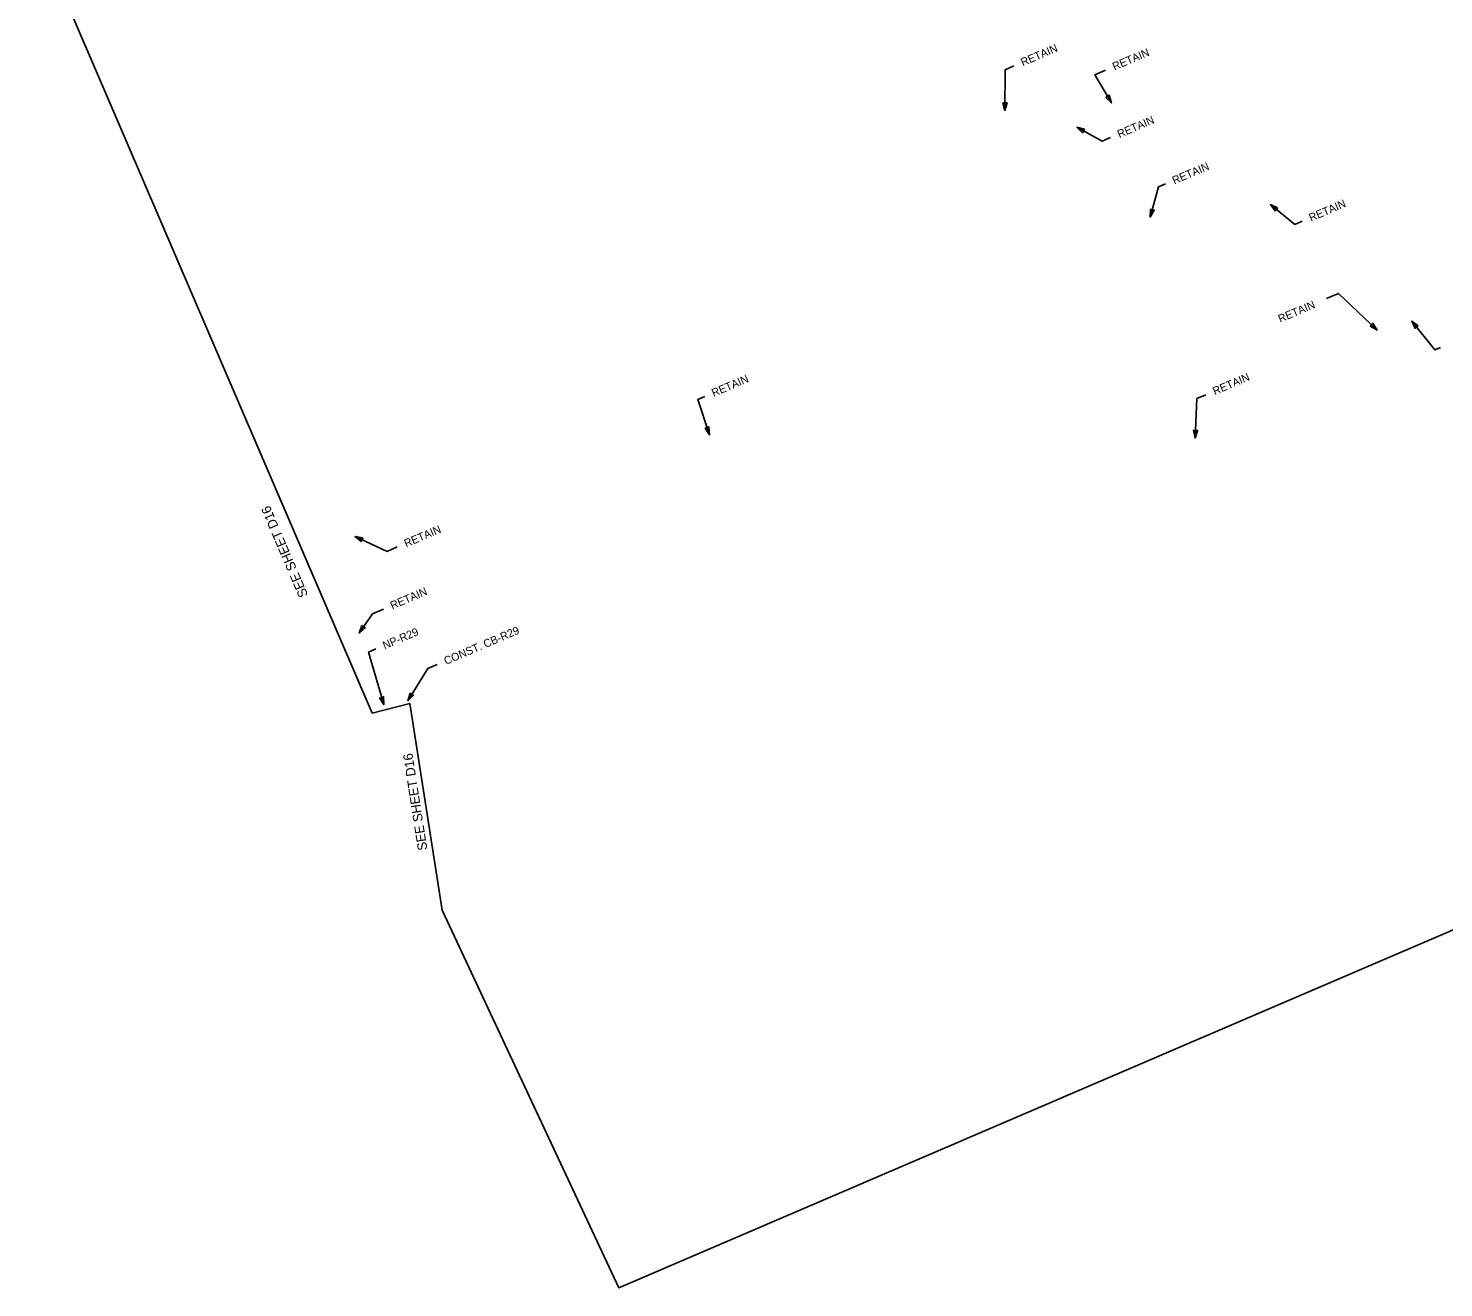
# Model space of a CAD drawing. Extents: x 1621083 to 1622865, y 1102384 to 1104005.
# Drawn here: x 1621083 to 1621976, y 1102384 to 1103179 of the extents above; entities that cross this region are included whole.
import ezdxf

# ---------------------------------------------------------------- set-up
doc = ezdxf.new("R2010")
doc.units = 0
for name, color, linetype in [('Level 8', 7, 'Continuous'), ('RD_HC_Data_Tic', 7, 'Continuous'), ('RFP', 7, 'Continuous')]:
    doc.layers.add(name, color=color, linetype=linetype)

msp = doc.modelspace()

# ---------------------------------------------------------------- linework, layer by layer
at = {"layer": 'Level 8'}
for points in [[(1621705.14, 1103155.41), (1621699.52, 1103153), (1621699.47, 1103127.29)], [(1621762.96, 1103152.74), (1621756.16, 1103149.82), (1621766.63, 1103132.03)], [(1621766.08, 1103110.09), (1621760.85, 1103107.84), (1621744.84, 1103116.66)], [(1621800.73, 1103080.85), (1621796.33, 1103078.96), (1621791.17, 1103059.95)], [(1621886.97, 1103057.32), (1621882.43, 1103055.37), (1621866.93, 1103067.88)], [(1621902.44, 1103008.5), (1621910, 1103011.74), (1621934.27, 1102988.65)], [(1621974.23, 1102977.64), (1621970.6, 1102976.08), (1621956.22, 1102994.32)], [(1621510.07, 1102946.72), (1621505.65, 1102944.83), (1621512.95, 1102922.47)], [(1621826.26, 1102947.82), (1621820.5, 1102945.35), (1621819.46, 1102920.51)], [(1621316.04, 1102851.73), (1621309.57, 1102848.95), (1621289.39, 1102858.31)], [(1621307.31, 1102812.53), (1621300.39, 1102809.56), (1621291.99, 1102797.4)], [(1621302.51, 1102787.33), (1621297.86, 1102785.33), (1621307.45, 1102752.2)], [(1621341.17, 1102777.53), (1621335.28, 1102775.01), (1621322.71, 1102754.68)]]:
    msp.add_lwpolyline(points, dxfattribs=at)
for points in [[(1621698.19, 1103132.12), (1621699.47, 1103127.29), (1621700.77, 1103132.12)], [(1621763.07, 1103135.53), (1621766.63, 1103132.03), (1621765.3, 1103136.84)], [(1621749.7, 1103115.46), (1621744.84, 1103116.66), (1621748.45, 1103113.19)], [(1621871.5, 1103065.85), (1621866.93, 1103067.88), (1621869.88, 1103063.84)], [(1621791.18, 1103064.95), (1621791.17, 1103059.95), (1621793.68, 1103064.27)], [(1621929.88, 1102991.04), (1621934.27, 1102988.65), (1621931.66, 1102992.91)], [(1621960.22, 1102991.33), (1621956.22, 1102994.32), (1621958.19, 1102989.72)], [(1621510.22, 1102926.66), (1621512.95, 1102922.47), (1621512.68, 1102927.46)], [(1621818.37, 1102925.39), (1621819.46, 1102920.51), (1621820.95, 1102925.28)], [(1621294.31, 1102857.45), (1621289.39, 1102858.31), (1621293.22, 1102855.1)], [(1621293.67, 1102802.11), (1621291.99, 1102797.4), (1621295.8, 1102800.63)], [(1621304.87, 1102756.48), (1621307.45, 1102752.2), (1621307.35, 1102757.2)], [(1621324.15, 1102759.47), (1621322.71, 1102754.68), (1621326.35, 1102758.11)]]:
    msp.add_lwpolyline(points, close=True, dxfattribs=at)
at = {"layer": 'RFP'}
msp.add_lwpolyline([(1621300.09, 1102746.85), (1621324.02, 1102752.88), (1621344.3, 1102622.52), (1621455.74, 1102384.16), (1622813.61, 1102966.94), (1622454.69, 1103803.24), (1622329.06, 1103749.66), (1622314.99, 1103780.87), (1621083.19, 1103252.2)], close=True, dxfattribs=at)
msp.add_lwpolyline([(1621300.09, 1102746.85), (1621324.02, 1102752.88), (1621344.3, 1102622.52), (1621455.74, 1102384.16), (1622813.61, 1102966.94), (1622454.69, 1103803.24), (1622329.06, 1103749.66), (1622314.99, 1103780.87), (1621083.19, 1103252.2)], close=True, dxfattribs=at)
msp.add_lwpolyline([(1621300.09, 1102746.85), (1621324.02, 1102752.88), (1621344.3, 1102622.52), (1621455.74, 1102384.16), (1622813.61, 1102966.94), (1622454.69, 1103803.24), (1622329.06, 1103749.66), (1622314.99, 1103780.87), (1621083.19, 1103252.2)], close=True, dxfattribs=at)
msp.add_lwpolyline([(1621300.09, 1102746.85), (1621324.02, 1102752.88), (1621344.3, 1102622.52), (1621455.74, 1102384.16), (1622813.61, 1102966.94), (1622454.69, 1103803.24), (1622329.06, 1103749.66), (1622314.99, 1103780.87), (1621083.19, 1103252.2)], close=True, dxfattribs=at)
msp.add_lwpolyline([(1621300.09, 1102746.85), (1621324.02, 1102752.88), (1621344.3, 1102622.52), (1621455.74, 1102384.16), (1622813.61, 1102966.94), (1622454.69, 1103803.24), (1622329.06, 1103749.66), (1622314.99, 1103780.87), (1621083.19, 1103252.2)], close=True, dxfattribs=at)

# ---------------------------------------------------------------- texts
at = {"layer": 'Level 8'}
for s, p in [('RETAIN', (1621710.72, 1103155.09)), ('RETAIN', (1621768.54, 1103152.42)), ('RETAIN', (1621771.66, 1103109.76)), ('RETAIN', (1621806.31, 1103080.52)), ('RETAIN', (1621892.55, 1103056.99)), ('RETAIN', (1621873.14, 1102993.2)), ('RETAIN', (1621515.65, 1102946.4)), ('RETAIN', (1621831.84, 1102947.5)), ('RETAIN', (1621321.62, 1102851.4)), ('RETAIN', (1621312.89, 1102812.2)), ('NP-R29', (1621308.09, 1102787)), ('CONST. CB-R29', (1621346.75, 1102777.21))]:
    msp.add_text(s, height=5, rotation=23.22835, dxfattribs=at).set_placement(p)
at = {"layer": 'RD_HC_Data_Tic'}
for rotation, p in [(113.22835, (1621259.86, 1102821.39)), (98.84251, (1621335.05, 1102660.63))]:
    msp.add_text('SEE SHEET D16', height=6, rotation=rotation, dxfattribs=at).set_placement(p)

doc.saveas('drawing.dxf')
